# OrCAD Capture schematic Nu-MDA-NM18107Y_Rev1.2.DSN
size A4; title: Nu-MDA-NM18107; rev: V1.1
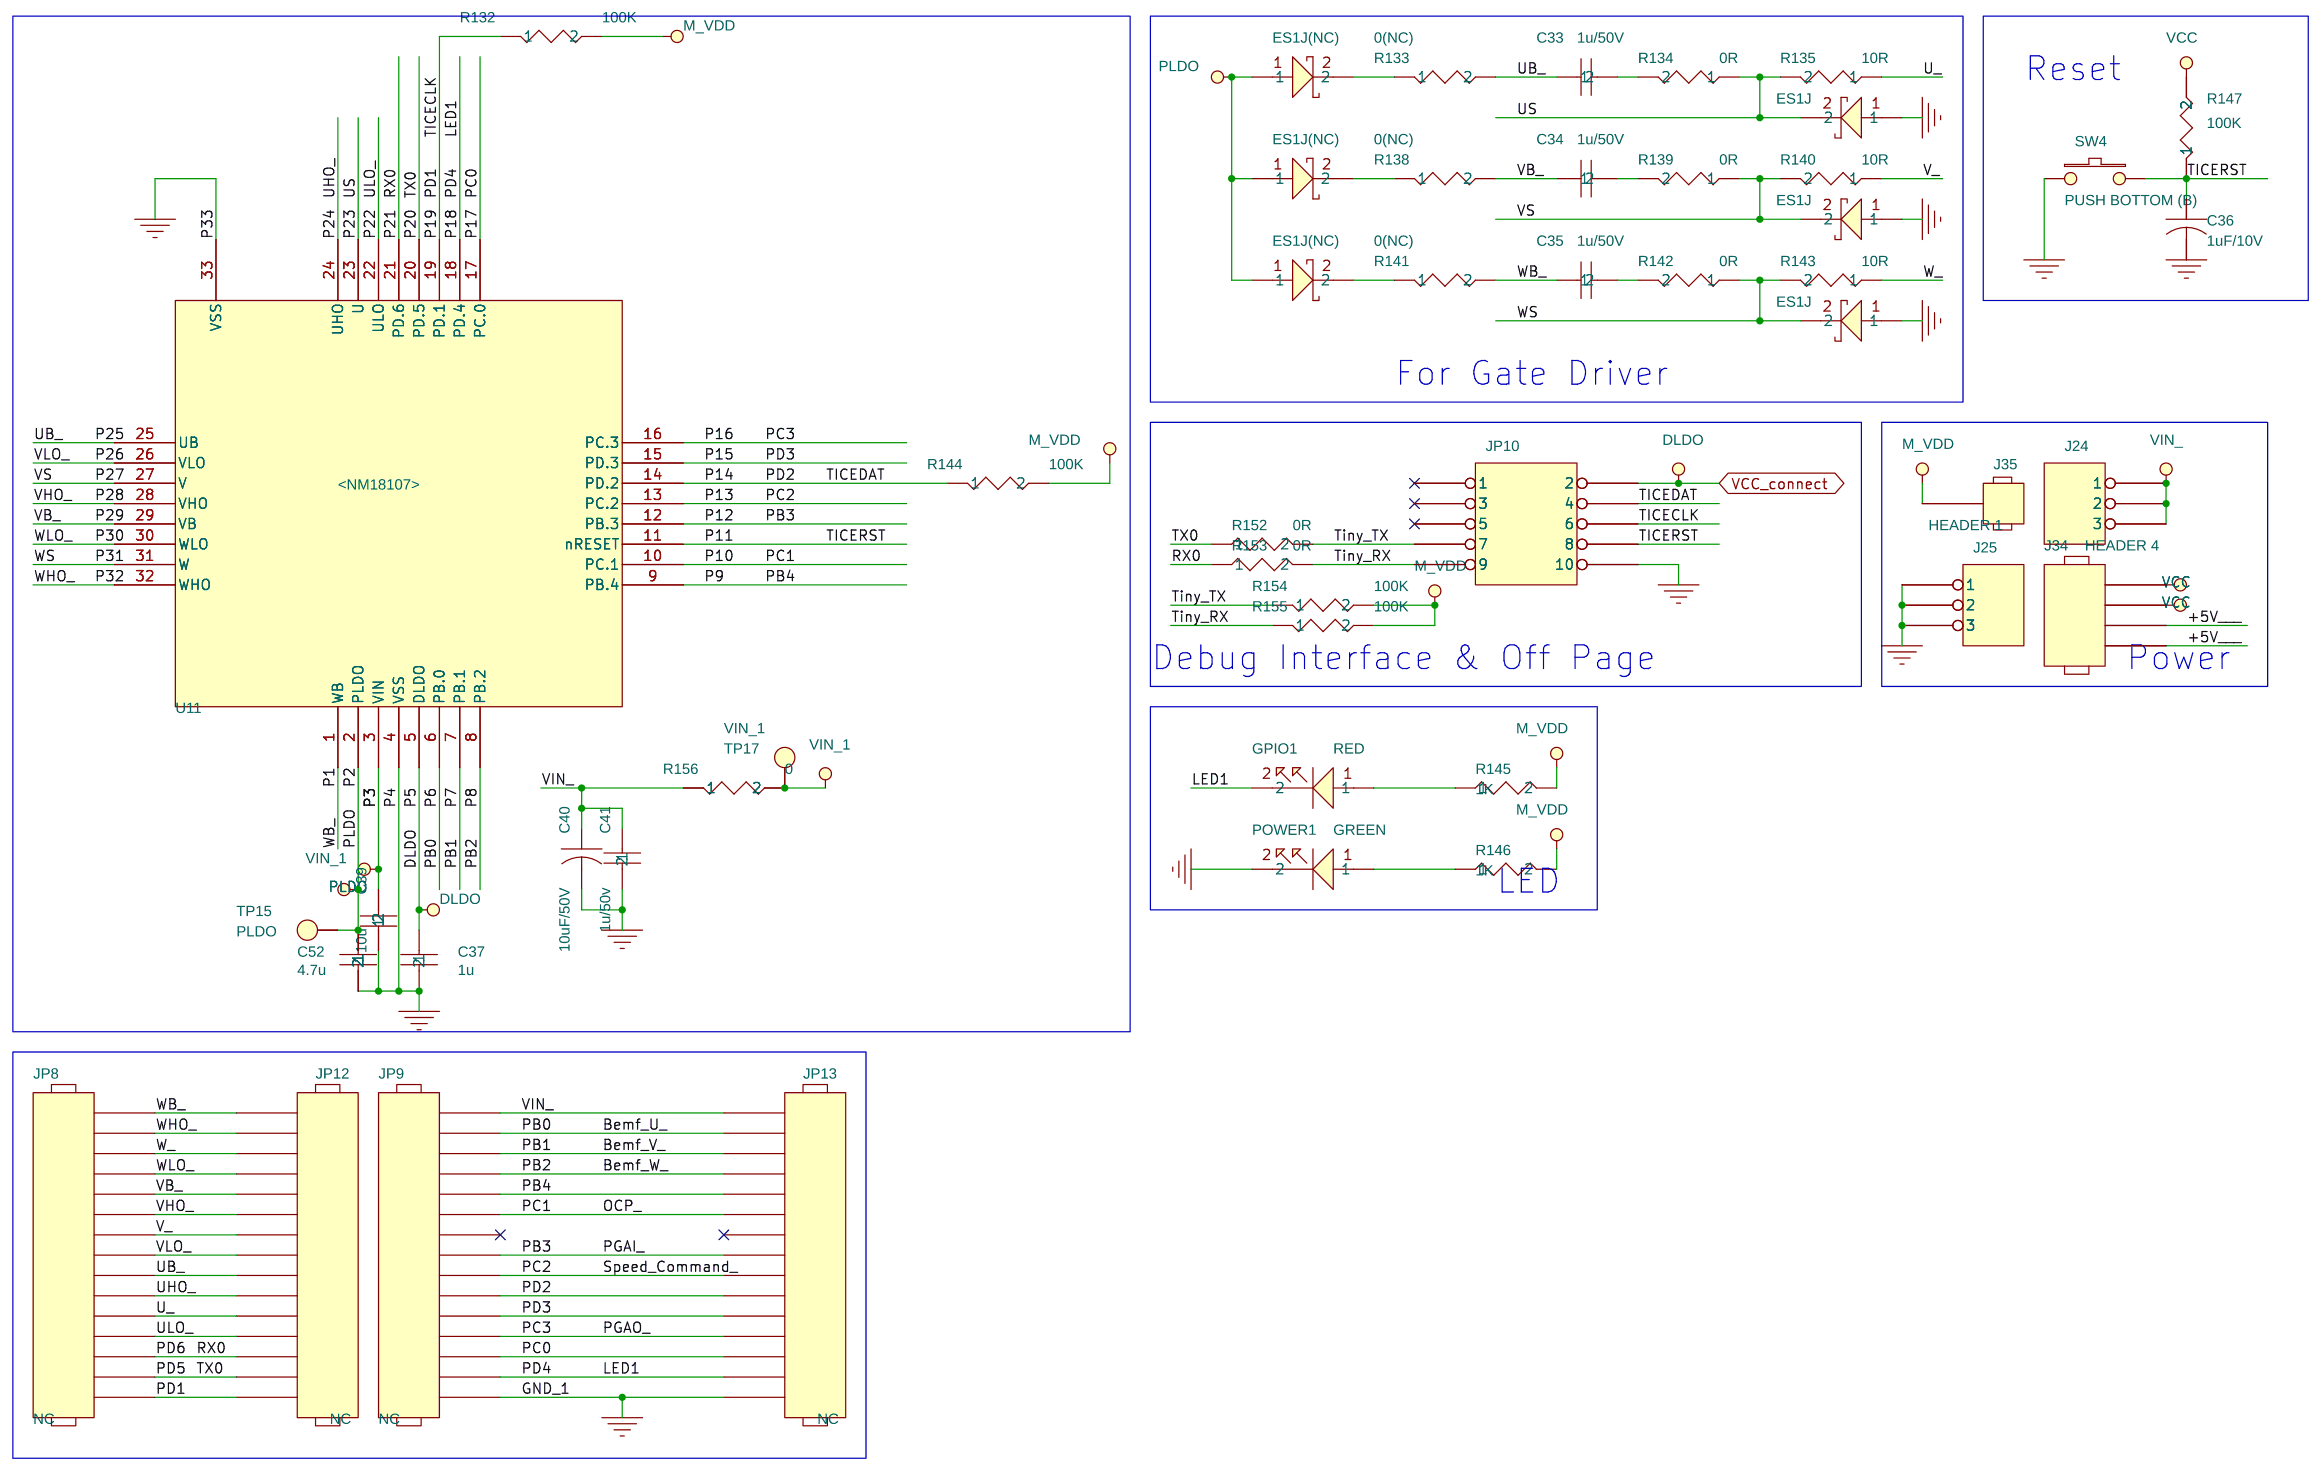
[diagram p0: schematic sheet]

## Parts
C33  1u/50V  [C0805]
C34  1u/50V  [C0805]
C35  1u/50V  [C0805]
C36  1uF/10V  [TANT-A]
C37  1u  [C0805]
C39  10u  [C0805]
C40  10uF/50V  [CAP_6_0.5]
C41  1u/50v  [C0805]
C52  4.7u  [C0805]
GPIO1  RED  [LED0805]
J24  NC  [header3]
J25  NC  [header3]
J34  HEADER 4  [HEADER1X4]
J35  HEADER 1  [SIP-1P]
JP8  NC  [HEADER15X1]
JP9  NC  [HEADER15X1]
JP10  NC  [HEADER5X2]
JP12  NC  [HEADER15X1]
JP13  NC  [HEADER15X1]
PD1  ES1J(NC)  [RB060L]
PD2  ES1J  [RB060L]
PD3  ES1J(NC)  [RB060L]
PD4  ES1J  [RB060L]
PD5  ES1J(NC)  [RB060L]
PD6  ES1J  [RB060L]
POWER1  GREEN  [LED0805]
R132  100K  [R0603]
R133  0(NC)  [R0805]
R134  0R  [R0603]
R135  10R  [R0603]
R138  0(NC)  [R0805]
R139  0R  [R0603]
R140  10R  [R0603]
R141  0(NC)  [R0805]
R142  0R  [R0603]
R143  10R  [R0603]
R144  100K  [R0603]
R145  1K  [R0603]
R146  1K  [R0603]
R147  100K  [R0603]
R152  0R  [R0603]
R153  0R  [R0603]
R154  100K  [R0603]
R155  100K  [R0603]
R156  0  [R0805]
SW4  PUSH BOTTOM (B)  [SW_SMD_HSM]
TP15  PLDO  [sip-1p]
TP17  VIN_1  [sip-1p]
U11  NM1200TBAE  [QFN32]

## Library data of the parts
C33 = C_1u_2
C34 = C_1u_3
C35 = C_1u_1
C36 C40 = C_10uF_10V
C37 = C_0.1u_2
C39 = C_1u
C41 = C_0.1u
C52 = C_0.1u_1
GPIO1 = LED_RED
J24 = HEADER_3_v2_1
J25 = HEADER_3_v2
J34 = HEADER_4
J35 = HEADER_1
JP8 JP9 JP12 JP13 = HEADER_15
JP10 = HEADER_5X2
PD1 = D_SS24A_2
PD2 = D_SS24A
PD3 = D_SS24A_1
PD4 = D_SS24A_5
PD5 = D_SS24A_3
PD6 = D_SS24A_4
POWER1 = LED_GREEN
R132 = R_100K_1
R133 = R_100K_8
R134 = R_10K
R135 = R_10K_1
R138 = R_100K_3
R139 = R_10K_2
R140 = R_10K_4
R141 = R_100K_5
R142 = R_10K_3
R143 = R_10K_5
R144 = R_100K_7
R145 = R_1K
R146 = R_1K_1
R147 = R_100K
R152 = R_0_1
R153 = R_0
R154 = R_100K_4
R155 = R_100K_6
R156 = R_100K_2
SW4 = PUSH_BOTTOM_(B)
TP15 TP17 = T_POINT_R
U11 = NM1200TBAE_12: NM1200TBAE: <NM18107>

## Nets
+5V___: J34.3 J34.4
GND_1: C36.2 C37.2 C39.1 C40.2 C41.2 C52.2 J25.1 J25.2 J25.3 JP9.15 JP10.10 JP13.15 PD2.1 PD4.1 PD6.1 POWER1.2 SW4.1 U11.4(VSS) U11.33(VSS)
VCC_connect: C37.1 J34.1 JP10.2 U11.5(DLDO)
VIN_: C40.1 C41.1 J24.1 J24.2 J24.3 JP9.1 JP13.1 R156.1
VIN_1: C39.2 R156.2 TP17.1(TP) U11.3(VIN)
Bemf_U_: JP9.2 JP13.2 U11.6(PB.0)
Bemf_V_: JP9.3 JP13.3 U11.7(PB.1)
Bemf_W_: JP9.4 JP13.4 U11.8(PB.2)
LED1: GPIO1.2 JP9.14 JP13.14 U11.18(PD.4)
M_VDD: J34.2 J35.1 R132.2 R144.2 R145.2 R146.2 R147.2 R154.2 R155.2
OCP_: JP9.6 JP13.6 U11.10(PC.1)
P1: C35.1 JP8.1 JP12.1 R141.2 U11.1(WB)
P9: JP9.5 JP13.5 U11.9(PB.4)
P11: C36.1 JP10.8 R147.1 SW4.2 U11.11(nRESET)
P12: JP9.8 JP13.8 U11.12(PB.3)
P13: JP9.9 JP13.9 U11.13(PC.2)
P14: JP9.10 JP10.4 JP13.10 R144.1 U11.14(PD.2)
P15: JP9.11 JP13.11 U11.15(PD.3)
P16: JP9.12 JP13.12 U11.16(PC.3)
P17: JP9.13 JP13.13 U11.17(PC.0)
P19: JP8.15 JP10.6 JP12.15 R132.1 U11.19(PD.1)
P20: JP8.14 JP12.14 R152.1 U11.20(PD.5)
P21: JP8.13 JP12.13 R153.1 U11.21(PD.6)
P22: JP8.12 JP12.12 U11.22(ULO)
P23: PD2.2 R134.1 R135.2 U11.23(U)
P24: JP8.10 JP12.10 U11.24(UHO)
P25: C33.1 JP8.9 JP12.9 R133.2 U11.25(UB)
P26: JP8.8 JP12.8 U11.26(VLO)
P27: PD4.2 R139.1 R140.2 U11.27(V)
P28: JP8.6 JP12.6 U11.28(VHO)
P29: C34.1 JP8.5 JP12.5 R138.2 U11.29(VB)
P30: JP8.4 JP12.4 U11.30(WLO)
P31: PD6.2 R142.1 R143.2 U11.31(W)
P32: JP8.2 JP12.2 U11.32(WHO)
PLDO: C52.1 PD1.1 PD3.1 PD5.1 TP15.1(TP) U11.2(PLDO)
Tiny_RX: JP10.9 R153.2 R155.1
Tiny_TX: JP10.7 R152.2 R154.1
U_: JP8.11 JP12.11 R135.1
V_: JP8.7 JP12.7 R140.1
W_: JP8.3 JP12.3 R143.1
N20657758: GPIO1.1 R145.1
N20657766: POWER1.1 R146.1
N20662918: C35.2 R142.2
N20672101: PD5.2 R141.1
N20675645: PD1.2 R133.1
N20675683: C33.2 R134.2
N20676030: PD3.2 R138.1
N20676049: C34.2 R139.2

Not connected (* = marked no-connect by the designer): JP9 7*; JP10 1* 3* 5*; JP13 7*

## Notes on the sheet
- Reset
- For Gate Driver
- Debug Interface & Off Page
- Power
- LED
